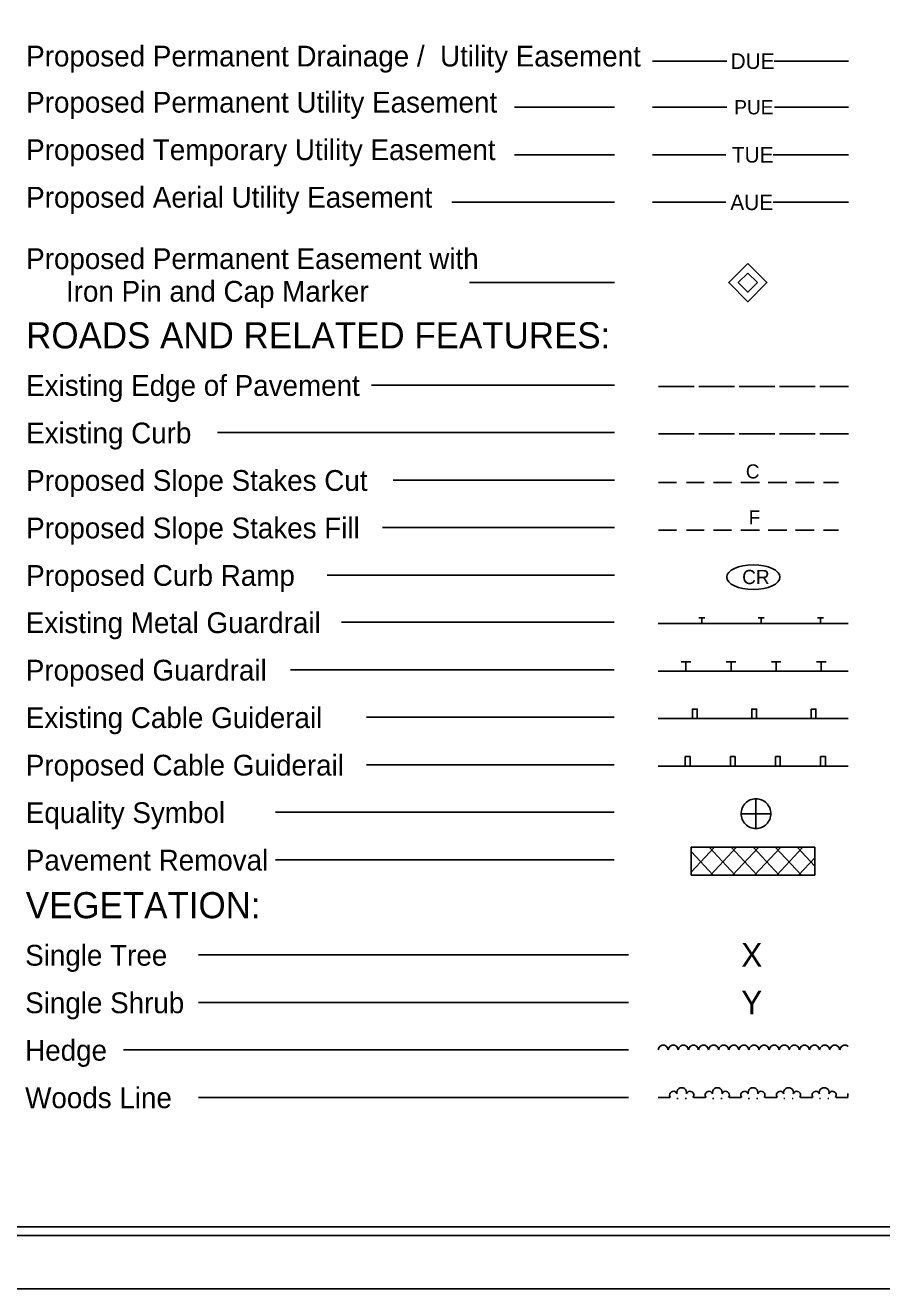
# Model space of a CAD drawing. Extents: x 1729679 to 1731363, y 539860 to 540960.
# Drawn here: x 1730240 to 1730601, y 539860 to 540392 of the extents above; entities that cross this region are included whole.
import ezdxf

# ---------------------------------------------------------------- set-up
doc = ezdxf.new("R2010")
doc.units = 0
for name, color, linetype in [('Prop Easement Permanent Drainage Utility', 7, 'Continuous'), ('Prop ROW Permanent Easement CELL', 7, 'Continuous'), ('Prop WCC CELL', 7, 'Continuous'), ('Sheet Plot Border Inside CELL', 7, 'Continuous'), ('Sheet Plot Border Outside CELL', 7, 'Continuous'), ('Sheet Symbology CELL', 7, 'Continuous')]:
    doc.layers.add(name, color=color, linetype=linetype)

msp = doc.modelspace()

# ---------------------------------------------------------------- linework, layer by layer
at = {"layer": 'Prop Easement Permanent Drainage Utility'}
for p, q in [((1730504.58, 540377.25), (1730535.88, 540377.25)), ((1730555.88, 540377.25), (1730587.08, 540377.25))]:
    msp.add_line(p, q, dxfattribs=at)
at = {"layer": 'Prop ROW Permanent Easement CELL'}
msp.add_line((1730544.72, 540284), (1730544.72, 540284), dxfattribs=at)
for points in [[(1730544.72, 540292.05), (1730552.77, 540283.99), (1730544.72, 540275.94), (1730536.67, 540283.99)], [(1730544.72, 540288.02), (1730548.75, 540283.99), (1730544.72, 540279.97), (1730540.7, 540283.99)]]:
    msp.add_lwpolyline(points, close=True, dxfattribs=at)
at = {"layer": 'Prop WCC CELL'}
msp.add_ellipse((1730547.04, 540159.97), major_axis=(11.21, 0), ratio=0.462467, dxfattribs=at)
at = {"layer": 'Sheet Plot Border Inside CELL'}
msp.add_lwpolyline([(1729692.08, 539882.79), (1731358.58, 539882.79), (1731358.58, 540937.89), (1729692.08, 540937.89)], close=True, dxfattribs=at)
at = {"layer": 'Sheet Plot Border Outside CELL'}
msp.add_lwpolyline([(1729679.08, 539860.34), (1731363.08, 539860.34), (1731363.08, 540960.34), (1729679.08, 540960.34)], close=True, dxfattribs=at)
at = {"layer": 'Sheet Symbology CELL'}
for p, q in [((1730488.55, 540357.82), (1730446.41, 540357.82)), ((1730504.58, 540357.82), (1730508.41, 540357.82)), ((1730508.41, 540357.82), (1730535.91, 540357.82)), ((1730555.91, 540357.82), (1730583.41, 540357.82)), ((1730583.41, 540357.82), (1730587.08, 540357.82)), ((1730488.55, 540337.82), (1730446.41, 540337.82)), ((1730504.58, 540337.82), (1730507.93, 540337.82)), ((1730507.93, 540337.82), (1730535.43, 540337.82)), ((1730555.43, 540337.82), (1730582.93, 540337.82)), ((1730582.93, 540337.82), (1730587.08, 540337.82)), ((1730488.55, 540317.82), (1730420.09, 540317.82)), ((1730504.58, 540317.82), (1730507.93, 540317.82)), ((1730507.93, 540317.82), (1730535.43, 540317.82)), ((1730555.43, 540317.82), (1730582.93, 540317.82)), ((1730582.93, 540317.82), (1730587.08, 540317.82)), ((1730488.55, 540283.99), (1730427.54, 540283.99)), ((1730488.55, 540240.84), (1730386.2, 540240.84)), ((1730507.08, 540240.26), (1730522.08, 540240.26)), ((1730524.08, 540240.26), (1730539.08, 540240.26)), ((1730541.08, 540240.26), (1730556.08, 540240.26)), ((1730558.08, 540240.26), (1730573.08, 540240.26)), ((1730575.08, 540240.26), (1730587.08, 540240.26)), ((1730488.55, 540220.84), (1730321.4, 540220.84)), ((1730507.08, 540220.26), (1730522.08, 540220.26)), ((1730524.08, 540220.26), (1730539.08, 540220.26)), ((1730541.08, 540220.26), (1730556.08, 540220.26)), ((1730558.08, 540220.26), (1730573.08, 540220.26)), ((1730575.08, 540220.26), (1730587.08, 540220.26)), ((1730488.55, 540200.84), (1730395.36, 540200.84)), ((1730507.08, 540199.79), (1730514.68, 540199.79)), ((1730526.38, 540199.79), (1730518.83, 540199.79)), ((1730537.88, 540199.79), (1730530.28, 540199.79)), ((1730549.63, 540199.79), (1730541.83, 540199.79)), ((1730561.08, 540199.79), (1730553.33, 540199.79)), ((1730572.63, 540199.79), (1730564.78, 540199.79)), ((1730582.93, 540199.79), (1730576.53, 540199.79)), ((1730488.55, 540180.84), (1730390.81, 540180.84)), ((1730507.08, 540179.79), (1730514.68, 540179.79)), ((1730526.38, 540179.79), (1730518.83, 540179.79)), ((1730537.88, 540179.79), (1730530.28, 540179.79)), ((1730549.63, 540179.79), (1730541.83, 540179.79)), ((1730561.08, 540179.79), (1730553.33, 540179.79)), ((1730572.63, 540179.79), (1730564.78, 540179.79)), ((1730582.93, 540179.79), (1730576.53, 540179.79)), ((1730488.55, 540160.84), (1730367.62, 540160.84)), ((1730488.39, 540140.96), (1730373.55, 540140.96)), ((1730506.92, 540140.38), (1730586.92, 540140.38)), ((1730524.06, 540142.88), (1730526.56, 540142.88)), ((1730525.31, 540140.38), (1730525.31, 540142.88)), ((1730549.06, 540142.88), (1730551.56, 540142.88)), ((1730550.31, 540140.38), (1730550.31, 540142.88)), ((1730574.06, 540142.88), (1730576.56, 540142.88)), ((1730575.31, 540140.38), (1730575.31, 540142.88)), ((1730516.65, 540124.33), (1730520.65, 540124.33)), ((1730518.65, 540120.38), (1730518.65, 540124.33)), ((1730535.65, 540124.33), (1730539.65, 540124.33)), ((1730537.65, 540120.38), (1730537.65, 540124.33)), ((1730554.65, 540124.33), (1730558.65, 540124.33)), ((1730556.65, 540120.38), (1730556.65, 540124.33)), ((1730573.65, 540124.33), (1730577.65, 540124.33)), ((1730575.65, 540120.38), (1730575.65, 540124.33)), ((1730488.39, 540120.96), (1730352.15, 540120.96)), ((1730586.92, 540120.38), (1730506.92, 540120.38)), ((1730488.39, 540100.96), (1730384.09, 540100.96)), ((1730506.92, 540100.38), (1730586.92, 540100.38)), ((1730488.39, 540080.96), (1730384.09, 540080.96)), ((1730506.92, 540080.38), (1730586.92, 540080.38)), ((1730548.15, 540066.62), (1730548.15, 540060.37)), ((1730488.39, 540060.96), (1730345.77, 540060.96)), ((1730541.9, 540060.37), (1730548.15, 540060.37)), ((1730548.15, 540060.37), (1730548.15, 540054.12)), ((1730548.15, 540060.37), (1730554.4, 540060.37)), ((1730520.87, 540046.24), (1730572.97, 540046.24)), ((1730520.87, 540034.54), (1730520.87, 540046.24)), ((1730520.87, 540045.64), (1730521.42, 540046.24)), ((1730520.87, 540035.69), (1730530.72, 540046.24)), ((1730530.12, 540034.54), (1730520.87, 540044.44)), ((1730539.42, 540034.54), (1730528.42, 540046.24)), ((1730529.02, 540034.54), (1730540.02, 540046.24)), ((1730548.67, 540034.54), (1730537.72, 540046.24)), ((1730538.27, 540034.54), (1730549.32, 540046.24)), ((1730557.97, 540034.54), (1730546.97, 540046.24)), ((1730547.57, 540034.54), (1730558.57, 540046.24)), ((1730567.27, 540034.54), (1730556.22, 540046.24)), ((1730556.87, 540034.54), (1730567.82, 540046.24)), ((1730572.97, 540038.29), (1730565.52, 540046.24)), ((1730572.97, 540046.24), (1730572.97, 540034.54)), ((1730488.39, 540040.96), (1730345.77, 540040.96)), ((1730566.12, 540034.54), (1730572.97, 540041.84)), ((1730572.97, 540034.54), (1730520.87, 540034.54)), ((1730494.53, 540000.89), (1730313.4, 540000.89)), ((1730494.53, 539980.89), (1730313.4, 539980.89)), ((1730507.22, 539961.84), (1730507.82, 539962.49)), ((1730507.82, 539962.49), (1730508.62, 539962.94)), ((1730508.62, 539962.94), (1730509.57, 539962.94)), ((1730509.57, 539962.94), (1730510.37, 539962.44)), ((1730510.37, 539962.44), (1730510.92, 539961.79)), ((1730511.47, 539961.84), (1730512.07, 539962.49)), ((1730512.07, 539962.49), (1730512.87, 539962.94)), ((1730512.87, 539962.94), (1730513.82, 539962.94)), ((1730513.82, 539962.94), (1730514.62, 539962.44)), ((1730514.62, 539962.44), (1730515.17, 539961.79)), ((1730515.72, 539961.84), (1730516.32, 539962.49)), ((1730516.32, 539962.49), (1730517.12, 539962.94)), ((1730517.12, 539962.94), (1730518.07, 539962.94)), ((1730518.07, 539962.94), (1730518.87, 539962.44)), ((1730518.87, 539962.44), (1730519.42, 539961.79)), ((1730519.97, 539961.84), (1730520.57, 539962.49)), ((1730520.57, 539962.49), (1730521.37, 539962.94)), ((1730521.37, 539962.94), (1730522.32, 539962.94)), ((1730522.32, 539962.94), (1730523.12, 539962.44)), ((1730523.12, 539962.44), (1730523.67, 539961.79)), ((1730524.22, 539961.84), (1730524.82, 539962.49)), ((1730524.82, 539962.49), (1730525.62, 539962.94)), ((1730525.62, 539962.94), (1730526.57, 539962.94)), ((1730526.57, 539962.94), (1730527.37, 539962.44)), ((1730527.37, 539962.44), (1730527.92, 539961.79)), ((1730528.47, 539961.84), (1730529.07, 539962.49)), ((1730529.07, 539962.49), (1730529.87, 539962.94)), ((1730529.87, 539962.94), (1730530.82, 539962.94)), ((1730530.82, 539962.94), (1730531.62, 539962.44)), ((1730531.62, 539962.44), (1730532.17, 539961.79)), ((1730532.72, 539961.84), (1730533.32, 539962.49)), ((1730533.32, 539962.49), (1730534.12, 539962.94)), ((1730534.12, 539962.94), (1730535.07, 539962.94)), ((1730535.07, 539962.94), (1730535.87, 539962.44)), ((1730535.87, 539962.44), (1730536.42, 539961.79)), ((1730536.97, 539961.84), (1730537.57, 539962.49)), ((1730537.57, 539962.49), (1730538.37, 539962.94)), ((1730538.37, 539962.94), (1730539.32, 539962.94)), ((1730539.32, 539962.94), (1730540.12, 539962.44)), ((1730540.12, 539962.44), (1730540.67, 539961.79)), ((1730541.22, 539961.84), (1730541.82, 539962.49)), ((1730541.82, 539962.49), (1730542.62, 539962.94)), ((1730542.62, 539962.94), (1730543.57, 539962.94)), ((1730543.57, 539962.94), (1730544.37, 539962.44)), ((1730544.37, 539962.44), (1730544.92, 539961.79)), ((1730545.47, 539961.84), (1730546.07, 539962.49)), ((1730546.07, 539962.49), (1730546.87, 539962.94)), ((1730546.87, 539962.94), (1730547.82, 539962.94)), ((1730547.82, 539962.94), (1730548.62, 539962.44)), ((1730548.62, 539962.44), (1730549.17, 539961.79)), ((1730549.72, 539961.84), (1730550.32, 539962.49)), ((1730550.32, 539962.49), (1730551.12, 539962.94)), ((1730551.12, 539962.94), (1730552.07, 539962.94)), ((1730552.07, 539962.94), (1730552.87, 539962.44)), ((1730552.87, 539962.44), (1730553.42, 539961.79)), ((1730553.97, 539961.84), (1730554.57, 539962.49)), ((1730554.57, 539962.49), (1730555.37, 539962.94)), ((1730555.37, 539962.94), (1730556.32, 539962.94)), ((1730556.32, 539962.94), (1730557.12, 539962.44)), ((1730557.12, 539962.44), (1730557.67, 539961.79)), ((1730558.22, 539961.84), (1730558.82, 539962.49)), ((1730558.82, 539962.49), (1730559.62, 539962.94)), ((1730559.62, 539962.94), (1730560.57, 539962.94)), ((1730560.57, 539962.94), (1730561.37, 539962.44)), ((1730561.37, 539962.44), (1730561.92, 539961.79)), ((1730562.47, 539961.84), (1730563.07, 539962.49)), ((1730563.07, 539962.49), (1730563.87, 539962.94)), ((1730563.87, 539962.94), (1730564.82, 539962.94)), ((1730564.82, 539962.94), (1730565.62, 539962.44)), ((1730565.62, 539962.44), (1730566.17, 539961.79)), ((1730566.72, 539961.84), (1730567.32, 539962.49)), ((1730567.32, 539962.49), (1730568.12, 539962.94)), ((1730568.12, 539962.94), (1730569.07, 539962.94)), ((1730569.07, 539962.94), (1730569.87, 539962.44)), ((1730569.87, 539962.44), (1730570.42, 539961.79)), ((1730570.97, 539961.84), (1730571.57, 539962.49)), ((1730571.57, 539962.49), (1730572.37, 539962.94)), ((1730572.37, 539962.94), (1730573.32, 539962.94)), ((1730573.32, 539962.94), (1730574.12, 539962.44)), ((1730574.12, 539962.44), (1730574.67, 539961.79)), ((1730575.22, 539961.84), (1730575.82, 539962.49)), ((1730575.82, 539962.49), (1730576.62, 539962.94)), ((1730576.62, 539962.94), (1730577.57, 539962.94)), ((1730577.57, 539962.94), (1730578.37, 539962.44)), ((1730578.37, 539962.44), (1730578.92, 539961.79)), ((1730579.47, 539961.84), (1730580.07, 539962.49)), ((1730580.07, 539962.49), (1730580.87, 539962.94)), ((1730580.87, 539962.94), (1730581.82, 539962.94)), ((1730581.82, 539962.94), (1730582.62, 539962.44)), ((1730582.62, 539962.44), (1730583.17, 539961.79)), ((1730583.72, 539961.84), (1730584.32, 539962.49)), ((1730584.32, 539962.49), (1730585.12, 539962.94)), ((1730585.12, 539962.94), (1730586.07, 539962.94)), ((1730586.07, 539962.94), (1730586.87, 539962.44)), ((1730586.87, 539962.44), (1730586.92, 539962.39)), ((1730494.53, 539960.89), (1730281.84, 539960.89)), ((1730506.92, 539960.89), (1730507.22, 539961.84)), ((1730510.92, 539961.79), (1730511.12, 539960.94)), ((1730511.17, 539960.89), (1730511.47, 539961.84)), ((1730515.17, 539961.79), (1730515.37, 539960.94)), ((1730515.42, 539960.89), (1730515.72, 539961.84)), ((1730519.42, 539961.79), (1730519.62, 539960.94)), ((1730519.67, 539960.89), (1730519.97, 539961.84)), ((1730523.67, 539961.79), (1730523.87, 539960.94)), ((1730523.92, 539960.89), (1730524.22, 539961.84)), ((1730527.92, 539961.79), (1730528.12, 539960.94)), ((1730528.17, 539960.89), (1730528.47, 539961.84)), ((1730532.17, 539961.79), (1730532.37, 539960.94)), ((1730532.42, 539960.89), (1730532.72, 539961.84)), ((1730536.42, 539961.79), (1730536.62, 539960.94)), ((1730536.67, 539960.89), (1730536.97, 539961.84)), ((1730540.67, 539961.79), (1730540.87, 539960.94)), ((1730540.92, 539960.89), (1730541.22, 539961.84)), ((1730544.92, 539961.79), (1730545.12, 539960.94)), ((1730545.17, 539960.89), (1730545.47, 539961.84)), ((1730549.17, 539961.79), (1730549.37, 539960.94)), ((1730549.42, 539960.89), (1730549.72, 539961.84)), ((1730553.42, 539961.79), (1730553.62, 539960.94)), ((1730553.67, 539960.89), (1730553.97, 539961.84)), ((1730557.67, 539961.79), (1730557.87, 539960.94)), ((1730557.92, 539960.89), (1730558.22, 539961.84)), ((1730561.92, 539961.79), (1730562.12, 539960.94)), ((1730562.17, 539960.89), (1730562.47, 539961.84)), ((1730566.17, 539961.79), (1730566.37, 539960.94)), ((1730566.42, 539960.89), (1730566.72, 539961.84)), ((1730570.42, 539961.79), (1730570.62, 539960.94)), ((1730570.67, 539960.89), (1730570.97, 539961.84)), ((1730574.67, 539961.79), (1730574.87, 539960.94)), ((1730574.92, 539960.89), (1730575.22, 539961.84)), ((1730578.92, 539961.79), (1730579.12, 539960.94)), ((1730579.17, 539960.89), (1730579.47, 539961.84)), ((1730583.17, 539961.79), (1730583.37, 539960.94)), ((1730583.42, 539960.89), (1730583.72, 539961.84)), ((1730494.53, 539940.89), (1730313.4, 539940.89)), ((1730506.92, 539940.89), (1730511.92, 539940.89)), ((1730514.87, 539940.39), (1730515.37, 539940.39)), ((1730518.37, 539940.39), (1730518.87, 539940.39)), ((1730521.92, 539940.89), (1730526.92, 539940.89)), ((1730529.87, 539940.39), (1730530.37, 539940.39)), ((1730533.37, 539940.39), (1730533.87, 539940.39)), ((1730536.92, 539940.89), (1730541.92, 539940.89)), ((1730544.87, 539940.39), (1730545.37, 539940.39)), ((1730548.37, 539940.39), (1730548.87, 539940.39)), ((1730551.92, 539940.89), (1730556.92, 539940.89)), ((1730559.87, 539940.39), (1730560.37, 539940.39)), ((1730563.37, 539940.39), (1730563.87, 539940.39)), ((1730566.92, 539940.89), (1730571.92, 539940.89)), ((1730574.87, 539940.39), (1730575.37, 539940.39)), ((1730578.37, 539940.39), (1730578.87, 539940.39)), ((1730581.92, 539940.89), (1730586.92, 539940.89))]:
    msp.add_line(p, q, dxfattribs=at)
for points in [[(1731346.08, 540935.34), (1729846.08, 540935.34), (1729846.08, 539886.35), (1731346.08, 539886.35)], [(1730521.4, 540100.38), (1730523.4, 540100.38), (1730523.4, 540104.38), (1730521.4, 540104.38)], [(1730546.4, 540100.38), (1730548.4, 540100.38), (1730548.4, 540104.38), (1730546.4, 540104.38)], [(1730571.4, 540100.38), (1730573.4, 540100.38), (1730573.4, 540104.38), (1730571.4, 540104.38)], [(1730518.38, 540084.38), (1730520.38, 540084.38), (1730520.38, 540080.38), (1730518.38, 540080.38)], [(1730537.38, 540084.38), (1730539.38, 540084.38), (1730539.38, 540080.38), (1730537.38, 540080.38)], [(1730556.38, 540084.38), (1730558.38, 540084.38), (1730558.38, 540080.38), (1730556.38, 540080.38)], [(1730575.38, 540084.38), (1730577.38, 540084.38), (1730577.38, 540080.38), (1730575.38, 540080.38)]]:
    msp.add_lwpolyline(points, close=True, dxfattribs=at)
for centre, radius, start, end in [((1730548.15, 540060.37), 6.25, 89.9944, 179.9989), ((1730548.15, 540060.37), 6.25, 359.9944, 89.9989), ((1730548.15, 540060.37), 6.25, 179.9944, 269.9989), ((1730548.15, 540060.37), 6.25, 269.9944, 359.9989), ((1730513.37, 539941.9), 1.58, 18.435, 219.2315), ((1730516.87, 539942.9), 2.06, 345.9638, 194.0362), ((1730520.37, 539941.9), 1.58, 320.7685, 161.5651), ((1730528.37, 539941.9), 1.58, 18.435, 219.2315), ((1730531.87, 539942.9), 2.06, 345.9638, 194.0362), ((1730535.37, 539941.9), 1.58, 320.7685, 161.5651), ((1730543.37, 539941.9), 1.58, 18.435, 219.2315), ((1730546.87, 539942.9), 2.06, 345.9638, 194.0362), ((1730550.37, 539941.9), 1.58, 320.7685, 161.5651), ((1730558.37, 539941.9), 1.58, 18.435, 219.2315), ((1730561.87, 539942.9), 2.06, 345.9638, 194.0362), ((1730565.37, 539941.9), 1.58, 320.7685, 161.5651), ((1730573.37, 539941.9), 1.58, 18.435, 219.2315), ((1730576.87, 539942.9), 2.06, 345.9638, 194.0362), ((1730580.37, 539941.9), 1.58, 320.7685, 161.5651), ((1730588.37, 539941.9), 1.58, 156.251, 203.749)]:
    msp.add_arc(centre, radius, start, end, dxfattribs=at)

# ---------------------------------------------------------------- texts
at = {"layer": 'Prop Easement Permanent Drainage Utility'}
msp.add_text('DUE', height=6.55, dxfattribs=at).set_placement((1730537.47, 540373.95))
at = {"layer": 'Prop WCC CELL'}
msp.add_text('CR', height=6, dxfattribs=at).set_placement((1730542.33, 540157.02))
at = {"layer": 'Sheet Symbology CELL'}
for s, height, p in [('Proposed Permanent Drainage /  Utility Easement', 8.75, (1730240.8, 540374.98)), ('Proposed Permanent Utility Easement', 8.75, (1730240.8, 540355.55)), ('PUE', 6, (1730539.01, 540354.82)), ('Proposed Temporary Utility Easement', 8.75, (1730240.8, 540335.55)), ('TUE', 6.55, (1730538.01, 540334.52)), ('Proposed Aerial Utility Easement', 8.75, (1730240.8, 540315.55)), ('AUE', 6.55, (1730537.35, 540314.52)), ('Proposed Permanent Easement with', 8.75, (1730240.8, 540289.69)), ('Iron Pin and Cap Marker', 8.75, (1730257.56, 540275.94)), ('ROADS AND RELATED FEATURES:', 11, (1730240.8, 540256.29)), ('Existing Edge of Pavement', 8.75, (1730240.8, 540236.29)), ('Existing Curb', 8.75, (1730240.8, 540216.29)), ('C', 5.93, (1730543.88, 540201.52)), ('Proposed Slope Stakes Cut', 8.75, (1730240.8, 540196.29)), ('F', 5.93, (1730545.08, 540182.15)), ('Proposed Slope Stakes Fill', 8.75, (1730240.8, 540176.29)), ('Proposed Curb Ramp', 8.75, (1730240.8, 540156.29)), ('Existing Metal Guardrail', 8.75, (1730240.64, 540136.41)), ('Proposed Guardrail', 8.75, (1730240.65, 540116.42)), ('Existing Cable Guiderail', 8.75, (1730240.65, 540096.42)), ('Proposed Cable Guiderail', 8.75, (1730240.65, 540076.42)), ('Equality Symbol', 8.75, (1730240.65, 540056.42)), ('Pavement Removal', 8.75, (1730240.65, 540036.42)), ('VEGETATION:', 11, (1730240.64, 540016.34)), ('Single Tree', 8.75, (1730240.37, 539996.36)), ('X', 10, (1730541.92, 539995.89)), ('Single Shrub', 8.75, (1730240.37, 539976.36)), ('Y', 10, (1730541.92, 539975.89)), ('Hedge', 8.75, (1730240.37, 539956.36)), ('Woods Line', 8.75, (1730240.37, 539936.36))]:
    msp.add_text(s, height=height, dxfattribs=at).set_placement(p)

doc.saveas('drawing.dxf')
